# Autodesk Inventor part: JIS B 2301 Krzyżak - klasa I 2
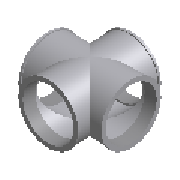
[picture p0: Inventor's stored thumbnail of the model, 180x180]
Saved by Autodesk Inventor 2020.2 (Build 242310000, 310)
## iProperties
Manager: www.cadconsulting.pl
Company: Fabian Stasiak CAD Consulting
Created: 2014-02
Part Number: JIS B 2301 Krzyżak - klasa I 2
Material: Żelazo, odlew
Description: Krzyżak
Document SubType Name: Modeling
Standard: JIS B 2301
Designer: F.Stasiak
Standards Organization: JIS
Language: pl-PL
Size Designation: 2
Categories: <MemberInstance><Categories><Category DisplayName="Rury cienko- i grubościenne" InternalName="4347fa0f-2144-441d-94cd-e3e15c92b736" Mnemonic="TUBEANDPIPE"><Cate
Density: 7.15 g/cm^3
Appearance: Ciemnoszary
Catalog Web Link: www.expertbooks.pl
IsCustomPart: 0
NAME: PIPING: JIS B 2301 Cross - Class I
DATA: <meta><inlinegroups number="2" deflen="26.4"></inlinegroups><connections number="4"></connections><angles><a>3.14159265358979</a><a>1.5707963267949</a><a>3.1415
Author: F.Stasiak
Subject: Zbiór ćwiczeń. Autodesk Inventor 2020. Kurs Professional
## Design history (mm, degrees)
sketch "Sketch1"
  geometry: L1 (0, 0)-(114, 0); L2 (114, 0)-(114, 28.328); L3 (114, 28.328)-(114, 36.5); L4 (114, 36.5)-(110, 36.5); L5 (110, 36.5)-(110, 34.5); L6 (110, 34.5)-(4, 34.5); L7 (57, 0)-(57, 34.5); L8 (0, 28.328)-(0, 36.5); L9 (0, 36.5)-(4, 36.5); L10 (4, 36.5)-(4, 34.5); L11 (0, 0)-(0, 28.328); L12 (21, 30.5)-(93, 30.5); L13 (21, 27.672)-(21, 30.5); L14 (93, 27.672)-(93, 30.5); L15 (0, 28.328)-(21, 27.672); L16 (93, 27.672)-(114, 28.328); L17 (21, 27.672)-(93, 27.672); L18 (21, 27.672)-(21, 0); 1 further point
  constraints: 36 end point, 5 perpendicular, 5 symmetric about line, 4 parallel, 2 midpoint, 1 coincident, 1 collinear, 1 horizontal, 1 point on line, 5 other
  dimensions: "d0" = 4 distance between parallel lines of L12 L6 (= t); "d1" = 4 distance of L8.end L9.end (= F1 - A1); "d2" = 57 distance between parallel lines of L7 L11 (= A); "d14" = 69 diameter of L6 L1 (= A1); "d15" = 73 diameter of L9 L1 (= F1); "d23" = 36 distance between parallel lines of L7 L13 (= Z1); "d24" = 1.78991 deg angle of L1 L15; "d25" = 56.656 diameter of L8.start L1 (= MD1)
revolve "Revolve1" sketch "Sketch1" stored, may be unused: angle "d5" = 90 deg
workplane "Work Plane1"
sketch "Sketch2"
  geometry: L1 (0, 0)-(114, 0) reference; L2 (57, 0)-(57, 34.5) reference; C1 r 34.5 at (57, 0)
  constraints: 1 centre point, 1 coincident
  dimensions: "d4" = 69 diameter of C1 (= A1)
extrude "Extrude1" join sketch "Sketch2" taper "d6" = 0 deg; stored distance "d9" = 10
sketch "Sketch3"
  geometry: C1 r 34.5 at (0, 0) reference; C2 r 36.5 at (0, 0)
  constraints: 1 centre point, 1 coincident, 1 concentric
  dimensions: "d7" = 73 diameter of C2 (= F1)
extrude "Extrude2" join sketch "Sketch3" distance "d8" = 4 (= F1 - A1); taper "d10" = 0 deg
mirror "Mirror1"
sketch "Sketch4"
  geometry: C1 r 36.5 at (0, 0) reference; C2 r 28.328 at (0, 0)
  constraints: 1 centre point, 1 coincident, 1 concentric
  dimensions: "d11" = 56.656 diameter of C2 (= MD1)
extrude "Extrude3" cut sketch "Sketch4" distance "d12" = 57 (= A); taper "d13" = -3.57633 deg
sketch "Sketch5"
  geometry: C1 r 36.5 at (0, 0) reference; C2 r 28.328 at (0, 0)
  constraints: 1 centre point, 1 coincident, 1 concentric
  dimensions: "d26" = 56.656 diameter of C2 (= MD1)
extrude "Extrude4" cut sketch "Sketch5" distance "d27" = 57 (= A); taper "d28" = -3.57633 deg
sketch "Sketch6"
  geometry: C1 r 30.5 at (57, 0); C2 r 28.328 at (57, 0) reference
  constraints: 1 centre point, 1 concentric
  dimensions: "d16" = 61 diameter of C1 (= A1 - 2 x t)
extrude "Extrude5" cut sketch "Sketch6" stored distance "d17" = 72 (= 2 x Z1); taper "d18" = 0 deg
workaxis "Work Axis1"
workpoint "Work Point1"
workpoint "Work Point2"
workaxis "Work Axis2"
workpoint "Work Point3"
workpoint "Work Point4"
workaxis "Work Axis3"
workpoint "Work Point5"
workpoint "Work Point6"
workaxis "Work Axis4"
workpoint "Work Point7"
workpoint "Work Point8"
body "Solid1"
feature "Gwint1" dims "d19" = 21 (= A - Z1), "d20" = 0
feature "Gwint2" dims "d36" = 21 (= A - Z1), "d37" = 0
feature "Gwint3" dims "d21" = 21 (= A - Z1), "d22" = 0
feature "Gwint4" dims "d40" = 21 (= A - Z1), "d41" = 0
other parameters: "A" = 57 [user parameter; used in 8 equation terms], "t" = 4 [user parameter; used in 2 equation terms], "d3" = 57 (= A), "MD1" = 56.656 [user parameter; used in 3 equation terms], "F1" = 73 [user parameter; used in 4 equation terms], "A1" = 69 [user parameter; used in 5 equation terms], "Z1" = 36 [user parameter; used in 6 equation terms]
